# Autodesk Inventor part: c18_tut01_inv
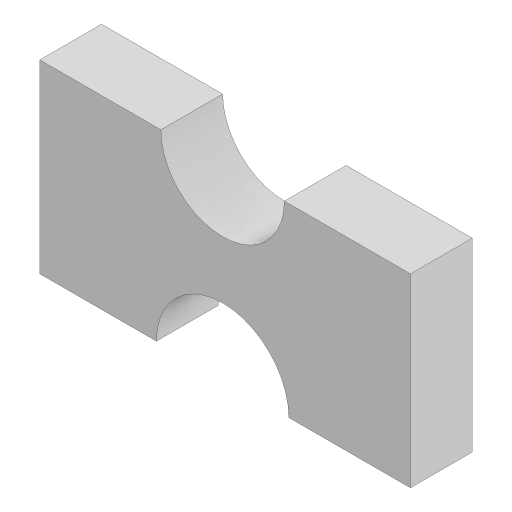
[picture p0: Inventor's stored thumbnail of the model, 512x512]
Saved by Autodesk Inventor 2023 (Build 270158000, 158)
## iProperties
Created: 2019-07
Part Number: c18_tut01_inv
Material: Generic
Document SubType Name: Modeling
Designer: LENOVO-CADCIM
Density: 1 g/cm^3
Appearance: Default
Author: LENOVO-CADCIM
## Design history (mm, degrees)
sketch "Sketch1"
  geometry: L1 (-29.598, 12.811)-(-10, 12.811); L2 (10, 12.811)-(30.402, 12.811); L3 (30.402, 12.811)-(30.402, -17.189); L4 (30.402, -17.189)-(10.723, -17.189); L5 (-10.723, -17.189)-(-29.598, -17.189); L6 (-29.598, -17.189)-(-29.598, 12.811); A1 r 10 centre (0, 12.811) between (-10, 12.811) and (10, 12.811); A2 r 10.723 centre (0, -17.189) between (10.723, -17.189) and (-10.723, -17.189); 1 further point
  constraints: 12 end point, 6 point on line, 4 point on circle, 3 perpendicular, 2 centre point, 1 horizontal
  dimensions: "d0" = 60 distance between parallel lines of L3 L6 (= LEN); "d1" = 30 distance of L5.end L1.start (= WID); "d2" = 10 radius of A1 (= RAD)
extrude "Extrusion1" new body sketch "Sketch1" distance "d3" = 10; taper "d4" = 0 deg
body "Solid1"
other parameters: "LEN" = 60 [user parameter; used in 4 equation terms], "WID" = 30 (= 0.5 x LEN) [user parameter; used in 1 equation term], "RAD" = 10 (= 0.166667 x LEN) [user parameter; used in 1 equation term]
